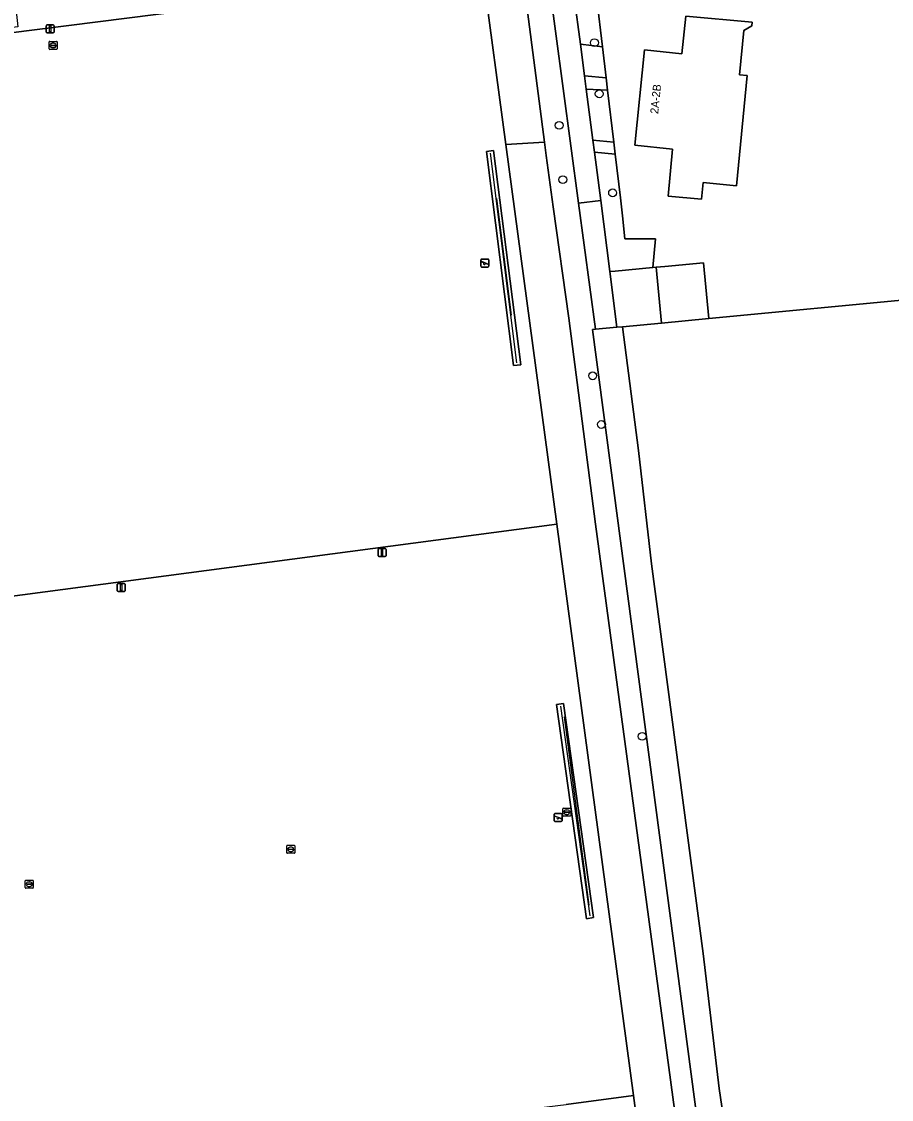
# Model space of a CAD drawing. Extents: x 162156 to 163172, y 378995 to 380779.
# Drawn here: x 162281 to 162389.7, y 380033.7 to 380168.4 of the extents above; entities that cross this region are included whole.
import ezdxf

# ---------------------------------------------------------------- set-up
doc = ezdxf.new("R2010")
doc.units = 0
for name, color, linetype in [('IMGEO_Boom', 7, 'Continuous'), ('IMGEO_Erf', 7, 'Continuous'), ('IMGEO_Gemengd_bos', 7, 'Continuous'), ('IMGEO_Groenvoorziening', 7, 'Continuous'), ('IMGEO_Hek', 7, 'Continuous'), ('IMGEO_Lichtmast', 7, 'Continuous'), ('IMGEO_Pand', 7, 'Continuous'), ('IMGEO_Pand_nummerreeks', 7, 'Continuous'), ('IMGEO_Rijbaan_lokaal_onverhard', 7, 'Continuous'), ('IMGEO_Rijbaan_lokaal_open', 7, 'Continuous'), ('IMGEO_Speelvoorziening', 7, 'Continuous'), ('IMGEO_Voetpad_open', 7, 'Continuous'), ('IMGEO_Waterleidingput', 7, 'Continuous')]:
    doc.layers.add(name, color=color, linetype=linetype)

msp = doc.modelspace()

# ---------------------------------------------------------------- linework, layer by layer
at = {"layer": 'IMGEO_Boom'}
for centre in [(162352.58, 380165.73), (162353.18, 380159.34), (162348.17, 380155.4), (162348.63, 380148.62), (162354.85, 380146.96), (162352.36, 380124.1), (162353.46, 380118.02), (162358.55, 380079.04)]:
    msp.add_circle(centre, 0.489, dxfattribs=at)
at = {"layer": 'IMGEO_Erf'}
msp.add_lwpolyline([(162352.89, 380171.18), (162353.59, 380165.23), (162354.05, 380161.34), (162354.23, 380159.8), (162355, 380153.3), (162355.18, 380151.8), (162355.82, 380146.36), (162356.09, 380144.08), (162356.39, 380141.22), (162360.23, 380141.23), (162359.88, 380137.62), (162360.28, 380137.66), (162361.4, 380137.77), (162366.23, 380138.22), (162366.89, 380131.26), (162393.17, 380133.77), (162390.9, 380150.84), (162392.48, 380150.86), (162395.9, 380167.06)], dxfattribs=at)
msp.add_lwpolyline([(162371.67, 380161.64), (162370.32, 380147.86), (162366.18, 380148.26), (162365.98, 380146.16), (162361.8, 380146.57), (162362.34, 380152.43), (162357.63, 380152.91), (162358.84, 380164.83), (162363.51, 380164.35), (162363.99, 380169.05), (162372.29, 380168.3), (162372.25, 380167.84), (162371.26, 380167.24), (162370.73, 380161.73)], close=True, dxfattribs=at)
at = {"layer": 'IMGEO_Gemengd_bos'}
msp.add_lwpolyline([(162393.17, 380133.77), (162366.89, 380131.26), (162360.95, 380130.69), (162356.07, 380130.23), (162358.08, 380114.77), (162359.7, 380100.61), (162366.19, 380051.88), (162368.19, 380035.01), (162373.39, 379999.97), (162377.92, 379964.17), (162380.66, 379943.74), (162385.55, 379907.89), (162386.78, 379896.21), (162387.59, 379889.87), (162388.51, 379884.81), (162389.32, 379882.03)], dxfattribs=at)
at = {"layer": 'IMGEO_Groenvoorziening'}
for points in [[(162408.08, 379703.18), (162408.29, 379704.23), (162408.36, 379710.92), (162407.43, 379718.66), (162402.67, 379750), (162400.56, 379766.6), (162399.53, 379777.44), (162398.6, 379783.51), (162394.07, 379815.93), (162388.91, 379854.45), (162387.25, 379866.95), (162383.98, 379890.99), (162369.54, 380000.04), (162352.33, 380129.87), (162352.7, 380129.91), (162350.59, 380145.67), (162344.82, 380188.69), (162344.72, 380189.46), (162342.57, 380189.18), (162342.12, 380191.72), (162328.74, 380188.44), (162317.98, 380185.47)], [(162289.2, 380186.22), (162277.89, 380189.11), (162278.44, 380184.1), (162278.77, 380184.14), (162278.76, 380184.27), (162292.3, 380181.3), (162302, 380178.94), (162304.98, 380178.29), (162308.61, 380177.85), (162309.98, 380177.93), (162316.17, 380179.08), (162342.22, 380185.05), (162346.32, 380153.31), (162346.54, 380151.63), (162347.44, 380145.21), (162349.39, 380131.32), (162352.73, 380105.57), (162366.95, 380000), (162368.46, 379988.67), (162368.62, 379987.48), (162371.68, 379964.61), (162386.53, 379853.64)], [(162362.05, 380000), (162357.46, 380034.17), (162349.06, 380033.03)]]:
    msp.add_lwpolyline(points, dxfattribs=at)
for points in [[(162338.63, 380174.45), (162341.5, 380153.01), (162346.32, 380153.31), (162342.22, 380185.05), (162316.17, 380179.08), (162309.98, 380177.93), (162308.61, 380177.85), (162304.98, 380178.29), (162302, 380178.94), (162292.3, 380181.3), (162278.76, 380184.27), (162278.77, 380184.14), (162280.52, 380167.72), (162235.53, 380161.77), (162231.09, 380161.19), (162231.13, 380160.83)], [(162347.88, 380105.55), (162341.5, 380153.01), (162338.63, 380174.45), (162231.13, 380160.83), (162234.01, 380138.54), (162234.55, 380138.6), (162235.45, 380138.74), (162239.5, 380111.99), (162238.6, 380111.85), (162237.47, 380111.68), (162239.09, 380099.1), (162240.1, 380091.32)], [(162353.59, 380165.23), (162350.82, 380165.53), (162351.34, 380161.57), (162354.05, 380161.34)], [(162354.23, 380159.8), (162351.55, 380159.94), (162352.39, 380153.57), (162355, 380153.3)], [(162352.73, 380105.57), (162349.39, 380131.32), (162347.44, 380145.21), (162346.54, 380151.63), (162346.32, 380153.31), (162341.5, 380153.01), (162347.88, 380105.55), (162357.46, 380034.17), (162362.05, 380000), (162363.64, 379988.01), (162368.46, 379988.67), (162366.95, 380000)], [(162339.09, 380152.15), (162339.98, 380152.27), (162343.37, 380125.46), (162342.47, 380125.37)], [(162355.82, 380146.36), (162355.18, 380151.8), (162352.6, 380152.04), (162353.39, 380146.02), (162354.49, 380137.12), (162355.17, 380137.18), (162359.88, 380137.62), (162360.23, 380141.23), (162356.39, 380141.22), (162356.09, 380144.08)], [(162347.88, 380105.55), (162240.1, 380091.32), (162242.86, 380069.86), (162243.55, 380069.94), (162244.44, 380070.04), (162245.36, 380062.21), (162247.61, 380043.14), (162246.72, 380043.04), (162246.32, 380043), (162249.3, 380019.9), (162250.63, 380020.07), (162305.6, 380027.79), (162349.06, 380033.03), (162357.46, 380034.17)], [(162347.84, 380083.04), (162348.71, 380083.16), (162352.48, 380056.38), (162351.6, 380056.25)]]:
    msp.add_lwpolyline(points, close=True, dxfattribs=at)
at = {"layer": 'IMGEO_Hek'}
for points in [[(162346.32, 380153.31), (162342.22, 380185.05)], [(162347.44, 380145.21), (162346.54, 380151.63), (162346.32, 380153.31)], [(162342.89, 380125.71), (162339.57, 380151.91)], [(162340.35, 380146.24), (162342.19, 380131.69)], [(162368.46, 379988.67), (162366.95, 380000), (162352.73, 380105.57), (162349.39, 380131.32), (162347.44, 380145.21)], [(162348.33, 380082.8), (162352.01, 380056.61)], [(162348.78, 380081.48), (162351.88, 380057.96)]]:
    msp.add_lwpolyline(points, dxfattribs=at)
at = {"layer": 'IMGEO_Lichtmast'}
for p, q in [((162284.05, 380167.06), (162284.05, 380167.86)), ((162284.05, 380167.86), (162284.05, 380167.06)), ((162284.15, 380167.96), (162284.94, 380167.96)), ((162284.94, 380167.96), (162284.15, 380167.96)), ((162285.04, 380167.86), (162285.04, 380167.06)), ((162285.04, 380167.06), (162285.04, 380167.86)), ((162284.94, 380166.96), (162284.15, 380166.96)), ((162284.15, 380166.96), (162284.94, 380166.96)), ((162325.54, 380101.61), (162325.54, 380102.41)), ((162325.54, 380102.41), (162325.54, 380101.61)), ((162325.64, 380102.51), (162326.43, 380102.51)), ((162326.43, 380102.51), (162325.64, 380102.51)), ((162326.53, 380102.41), (162326.53, 380101.61)), ((162326.53, 380101.61), (162326.53, 380102.41)), ((162326.43, 380101.51), (162325.64, 380101.51)), ((162325.64, 380101.51), (162326.43, 380101.51)), ((162292.94, 380097.24), (162292.94, 380098.04)), ((162292.94, 380098.04), (162292.94, 380097.24)), ((162293.04, 380098.14), (162293.83, 380098.14)), ((162293.83, 380098.14), (162293.04, 380098.14)), ((162293.93, 380098.04), (162293.93, 380097.24)), ((162293.93, 380097.24), (162293.93, 380098.04)), ((162293.83, 380097.14), (162293.04, 380097.14)), ((162293.04, 380097.14), (162293.83, 380097.14))]:
    msp.add_line(p, q, dxfattribs=at)
for points in [[(162284.47, 380167.84), (162284.62, 380167.84), (162284.62, 380167.09), (162284.47, 380167.09), (162284.47, 380167.84)], [(162325.96, 380102.39), (162326.11, 380102.39), (162326.11, 380101.64), (162325.96, 380101.64), (162325.96, 380102.39)], [(162293.36, 380098.02), (162293.51, 380098.02), (162293.51, 380097.27), (162293.36, 380097.27), (162293.36, 380098.02)]]:
    msp.add_lwpolyline(points, dxfattribs=at)
for centre, start, end in [((162284.15, 380167.86), 90, 180), ((162284.15, 380167.86), 90, 180), ((162284.94, 380167.86), 0, 90), ((162284.94, 380167.86), 360, 90), ((162284.15, 380167.06), 180, 270), ((162284.15, 380167.06), 180, 270), ((162284.94, 380167.06), 270, 0), ((162284.94, 380167.06), 270, 0), ((162325.64, 380102.41), 90, 180), ((162325.64, 380102.41), 90, 180), ((162326.43, 380102.41), 0, 90), ((162326.43, 380102.41), 360, 90), ((162325.64, 380101.61), 180, 270), ((162325.64, 380101.61), 180, 270), ((162326.43, 380101.61), 270, 0), ((162326.43, 380101.61), 270, 0), ((162293.04, 380098.04), 90, 180), ((162293.04, 380098.04), 90, 180), ((162293.83, 380098.04), 0, 90), ((162293.83, 380098.04), 360, 90), ((162293.04, 380097.24), 180, 270), ((162293.04, 380097.24), 180, 270), ((162293.83, 380097.24), 270, 0), ((162293.83, 380097.24), 270, 0)]:
    msp.add_arc(centre, 0.1, start, end, dxfattribs=at)
at = {"layer": 'IMGEO_Pand'}
for points in [[(162371.67, 380161.64), (162370.73, 380161.73), (162371.26, 380167.24), (162372.25, 380167.84), (162372.29, 380168.3), (162363.99, 380169.05), (162363.51, 380164.35), (162358.84, 380164.83), (162357.63, 380152.91), (162362.34, 380152.43), (162361.8, 380146.57), (162365.98, 380146.16), (162366.18, 380148.26), (162370.32, 380147.86)], [(162360.95, 380130.69), (162366.89, 380131.26), (162366.23, 380138.22), (162361.4, 380137.77), (162360.28, 380137.66)]]:
    msp.add_lwpolyline(points, close=True, dxfattribs=at)
at = {"layer": 'IMGEO_Rijbaan_lokaal_onverhard'}
msp.add_lwpolyline([(162388.51, 379884.81), (162387.59, 379889.87), (162386.78, 379896.21), (162385.55, 379907.89), (162380.66, 379943.74), (162377.92, 379964.17), (162373.39, 379999.97), (162368.19, 380035.01), (162366.19, 380051.88), (162359.7, 380100.61), (162358.08, 380114.77), (162356.07, 380130.23), (162355.36, 380130.16), (162352.7, 380129.91), (162352.33, 380129.87), (162369.54, 380000.04), (162383.98, 379890.99), (162387.25, 379866.95)], dxfattribs=at)
at = {"layer": 'IMGEO_Rijbaan_lokaal_open'}
for points in [[(162350.04, 380171.42), (162347.73, 380188.91), (162347.63, 380189.66), (162344.72, 380189.46), (162344.82, 380188.69), (162350.59, 380145.67), (162353.39, 380146.02), (162352.6, 380152.04), (162352.39, 380153.57), (162351.55, 380159.94), (162351.34, 380161.57), (162350.82, 380165.53)], [(162352.7, 380129.91), (162355.36, 380130.16), (162354.49, 380137.12), (162353.39, 380146.02), (162350.59, 380145.67)]]:
    msp.add_lwpolyline(points, close=True, dxfattribs=at)
at = {"layer": 'IMGEO_Speelvoorziening'}
for p, q in [((162338.38, 380137.79), (162338.38, 380138.59)), ((162338.38, 380138.59), (162338.38, 380137.79)), ((162338.77, 380138.22), (162338.43, 380138.36)), ((162338.45, 380138.42), (162339.33, 380138.07)), ((162338.48, 380138.69), (162339.27, 380138.69)), ((162339.27, 380138.69), (162338.48, 380138.69)), ((162339.37, 380138.59), (162339.37, 380137.79)), ((162339.37, 380137.79), (162339.37, 380138.59)), ((162339.27, 380137.69), (162338.48, 380137.69)), ((162338.48, 380137.69), (162339.27, 380137.69)), ((162339.3, 380138), (162338.96, 380138.14)), ((162347.55, 380068.5), (162347.55, 380069.3)), ((162347.55, 380069.3), (162347.55, 380068.5)), ((162347.93, 380068.93), (162347.59, 380069.06)), ((162347.61, 380069.12), (162348.49, 380068.77)), ((162347.65, 380069.4), (162348.43, 380069.4)), ((162348.43, 380069.4), (162347.65, 380069.4)), ((162348.43, 380068.4), (162347.65, 380068.4)), ((162347.65, 380068.4), (162348.43, 380068.4)), ((162348.47, 380068.71), (162348.13, 380068.85)), ((162348.53, 380069.3), (162348.53, 380068.5)), ((162348.53, 380068.5), (162348.53, 380069.3))]:
    msp.add_line(p, q, dxfattribs=at)
for centre, radius, start, end in [((162338.48, 380138.59), 0.1, 90, 180), ((162338.48, 380138.59), 0.1, 90, 180), ((162338.44, 380138.39), 0.0327, 68.078, 248.078), ((162338.84, 380138.13), 0.12, 130.9928, 5.1632), ((162339.27, 380138.59), 0.1, 0, 90), ((162339.27, 380138.59), 0.1, 360, 90), ((162338.48, 380137.79), 0.1, 180, 270), ((162338.48, 380137.79), 0.1, 180, 270), ((162339.27, 380137.79), 0.1, 270, 0), ((162339.27, 380137.79), 0.1, 270, 0), ((162339.32, 380138.04), 0.0327, 248.078, 68.078), ((162347.65, 380069.3), 0.1, 90, 180), ((162347.65, 380069.3), 0.1, 90, 180), ((162347.65, 380068.5), 0.1, 180, 270), ((162347.65, 380068.5), 0.1, 180, 270), ((162347.6, 380069.09), 0.0327, 68.078, 248.078), ((162348.01, 380068.83), 0.12, 130.9928, 5.1632), ((162348.43, 380069.3), 0.1, 0, 90), ((162348.43, 380069.3), 0.1, 360, 90), ((162348.43, 380068.5), 0.1, 270, 0), ((162348.43, 380068.5), 0.1, 270, 0), ((162348.48, 380068.74), 0.0327, 248.078, 68.078)]:
    msp.add_arc(centre, radius, start, end, dxfattribs=at)
at = {"layer": 'IMGEO_Voetpad_open'}
for points in [[(162352.89, 380171.18), (162350.04, 380171.42), (162350.82, 380165.53), (162353.59, 380165.23)], [(162354.05, 380161.34), (162351.34, 380161.57), (162351.55, 380159.94), (162354.23, 380159.8)], [(162355, 380153.3), (162352.39, 380153.57), (162352.6, 380152.04), (162355.18, 380151.8)], [(162343.37, 380125.46), (162339.98, 380152.27), (162339.09, 380152.15), (162342.47, 380125.37)], [(162355.36, 380130.16), (162356.07, 380130.23), (162360.95, 380130.69), (162360.28, 380137.66), (162359.88, 380137.62), (162355.17, 380137.18), (162354.49, 380137.12)], [(162352.48, 380056.38), (162348.71, 380083.16), (162347.84, 380083.04), (162351.6, 380056.25)]]:
    msp.add_lwpolyline(points, close=True, dxfattribs=at)
at = {"layer": 'IMGEO_Waterleidingput'}
for p, q in [((162284.42, 380164.97), (162284.42, 380165.82)), ((162284.49, 380165.89), (162285.35, 380165.89)), ((162284.68, 380165.39), (162284.68, 380165.4)), ((162284.72, 380165.44), (162285.12, 380165.44)), ((162285.12, 380165.35), (162284.72, 380165.35)), ((162284.91, 380165.67), (162284.93, 380165.67)), ((162285.16, 380165.4), (162285.16, 380165.39)), ((162285.42, 380165.82), (162285.42, 380164.97)), ((162285.35, 380164.89), (162284.49, 380164.89)), ((162284.93, 380165.11), (162284.9, 380165.11)), ((162348.62, 380069.13), (162348.62, 380069.99)), ((162348.7, 380070.06), (162349.55, 380070.06)), ((162348.88, 380069.55), (162348.88, 380069.57)), ((162349.32, 380069.52), (162348.92, 380069.52)), ((162348.93, 380069.6), (162349.32, 380069.6)), ((162349.11, 380069.84), (162349.14, 380069.84)), ((162349.37, 380069.57), (162349.37, 380069.55)), ((162349.63, 380069.99), (162349.63, 380069.13)), ((162349.55, 380069.06), (162348.7, 380069.06)), ((162349.13, 380069.28), (162349.11, 380069.28)), ((162314.13, 380064.49), (162314.13, 380065.35)), ((162314.2, 380065.42), (162315.06, 380065.42)), ((162315.06, 380064.42), (162314.2, 380064.42)), ((162314.39, 380064.91), (162314.39, 380064.93)), ((162314.43, 380064.96), (162314.83, 380064.96)), ((162314.83, 380064.88), (162314.43, 380064.88)), ((162314.62, 380065.2), (162314.64, 380065.2)), ((162314.64, 380064.64), (162314.62, 380064.64)), ((162314.87, 380064.93), (162314.87, 380064.91)), ((162315.13, 380065.35), (162315.13, 380064.49)), ((162281.44, 380060.14), (162281.44, 380060.99)), ((162281.52, 380061.06), (162282.37, 380061.06)), ((162281.7, 380060.56), (162281.7, 380060.57)), ((162282.14, 380060.52), (162281.74, 380060.52)), ((162281.75, 380060.61), (162282.14, 380060.61)), ((162281.93, 380060.84), (162281.96, 380060.84)), ((162281.95, 380060.28), (162281.93, 380060.28)), ((162282.19, 380060.57), (162282.19, 380060.56)), ((162282.45, 380060.99), (162282.45, 380060.14)), ((162282.37, 380060.06), (162281.52, 380060.06))]:
    msp.add_line(p, q, dxfattribs=at)
for points in [[(162284.42, 380164.97), (162284.42, 380165.82)], [(162284.49, 380165.89), (162285.35, 380165.89)], [(162285.42, 380165.82), (162285.42, 380164.97)], [(162285.35, 380164.89), (162284.49, 380164.89)], [(162348.62, 380069.13), (162348.62, 380069.99)], [(162348.7, 380070.06), (162349.55, 380070.06)], [(162349.63, 380069.99), (162349.63, 380069.13)], [(162349.55, 380069.06), (162348.7, 380069.06)], [(162314.13, 380064.49), (162314.13, 380065.35)], [(162314.2, 380065.42), (162315.06, 380065.42)], [(162315.06, 380064.42), (162314.2, 380064.42)], [(162315.13, 380065.35), (162315.13, 380064.49)], [(162281.44, 380060.14), (162281.44, 380060.99)], [(162281.52, 380061.06), (162282.37, 380061.06)], [(162282.45, 380060.99), (162282.45, 380060.14)], [(162282.37, 380060.06), (162281.52, 380060.06)]]:
    msp.add_lwpolyline(points, dxfattribs=at)
for centre, radius, start, end in [((162284.5, 380165.82), 0.0765, 91.552, 178.448), ((162284.5, 380165.82), 0.0765, 91.552, 178.448), ((162284.72, 380165.4), 0.0403, 85.8775, 175.7526), ((162284.71, 380165.39), 0.0366, 178.938, 274.7102), ((162285.12, 380165.4), 0.0386, 1.7309, 96.639), ((162285.12, 380165.39), 0.043, 264.8664, 352.4533), ((162285.34, 380165.82), 0.0765, 1.552, 88.448), ((162285.34, 380165.82), 0.0765, 1.552, 88.448), ((162284.5, 380164.97), 0.0765, 181.552, 268.448), ((162284.5, 380164.97), 0.0765, 181.552, 268.448), ((162285.34, 380164.97), 0.0765, 271.552, 358.448), ((162285.34, 380164.97), 0.0765, 271.552, 358.448), ((162348.7, 380069.98), 0.0765, 91.552, 178.448), ((162348.7, 380069.98), 0.0765, 91.552, 178.448), ((162348.92, 380069.56), 0.0403, 85.8775, 175.7526), ((162348.92, 380069.55), 0.0366, 178.938, 274.7102), ((162349.33, 380069.56), 0.0386, 1.7309, 96.639), ((162349.32, 380069.56), 0.043, 264.8664, 352.4533), ((162349.55, 380069.98), 0.0765, 1.552, 88.448), ((162349.55, 380069.98), 0.0765, 1.552, 88.448), ((162348.7, 380069.14), 0.0765, 181.552, 268.448), ((162348.7, 380069.14), 0.0765, 181.552, 268.448), ((162349.55, 380069.14), 0.0765, 271.552, 358.448), ((162349.55, 380069.14), 0.0765, 271.552, 358.448), ((162314.21, 380065.34), 0.0765, 91.552, 178.448), ((162314.21, 380065.34), 0.0765, 91.552, 178.448), ((162314.21, 380064.5), 0.0765, 181.552, 268.448), ((162314.21, 380064.5), 0.0765, 181.552, 268.448), ((162314.43, 380064.92), 0.0403, 85.8775, 175.7526), ((162314.43, 380064.91), 0.0366, 178.938, 274.7102), ((162314.83, 380064.92), 0.0386, 1.7309, 96.639), ((162314.83, 380064.92), 0.043, 264.8664, 352.4533), ((162315.05, 380065.34), 0.0765, 1.552, 88.448), ((162315.05, 380065.34), 0.0765, 1.552, 88.448), ((162315.05, 380064.5), 0.0765, 271.552, 358.448), ((162315.05, 380064.5), 0.0765, 271.552, 358.448), ((162281.52, 380060.99), 0.0765, 91.552, 178.448), ((162281.52, 380060.99), 0.0765, 91.552, 178.448), ((162281.52, 380060.14), 0.0765, 181.552, 268.448), ((162281.52, 380060.14), 0.0765, 181.552, 268.448), ((162281.74, 380060.57), 0.0403, 85.8775, 175.7526), ((162281.74, 380060.56), 0.0366, 178.938, 274.7102), ((162282.15, 380060.57), 0.0386, 1.7309, 96.639), ((162282.14, 380060.56), 0.043, 264.8664, 352.4533), ((162282.37, 380060.99), 0.0765, 1.552, 88.448), ((162282.37, 380060.99), 0.0765, 1.552, 88.448), ((162282.37, 380060.14), 0.0765, 271.552, 358.448), ((162282.37, 380060.14), 0.0765, 271.552, 358.448)]:
    msp.add_arc(centre, radius, start, end, dxfattribs=at)
for centre, major_axis, ratio, start_param, end_param in [((162284.91, 380165.39), (-0.387, 0.002), 0.722429, 4.712389, 7.853982), ((162284.93, 380165.39), (-0.39, 0.002), 0.717154, 1.570796, 4.712389), ((162349.11, 380069.56), (-0.387, 0.002), 0.722429, 4.712389, 7.853982), ((162349.14, 380069.56), (-0.39, 0.002), 0.717154, 1.570796, 4.712389), ((162314.62, 380064.92), (-0.387, 0.002), 0.722429, 4.712389, 7.853982), ((162314.64, 380064.92), (-0.39, 0.002), 0.717154, 1.570796, 4.712389), ((162281.93, 380060.56), (-0.387, 0.002), 0.722429, 4.712389, 7.853982), ((162281.96, 380060.56), (-0.39, 0.002), 0.717154, 1.570796, 4.712389)]:
    msp.add_ellipse(centre, major_axis=major_axis, ratio=ratio, start_param=start_param, end_param=end_param, dxfattribs=at)

# ---------------------------------------------------------------- texts
at = {"layer": 'IMGEO_Pand_nummerreeks'}
msp.add_text('2A-2B', height=1, rotation=84.2019, dxfattribs=at).set_placement((162360.54, 380156.8))

doc.saveas('drawing.dxf')
